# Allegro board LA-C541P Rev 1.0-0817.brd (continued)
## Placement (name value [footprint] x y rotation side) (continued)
CC192  1U_0402_6.3V6K  [C_0402]  197.4 74.87 90 bottom
CC193  1U_0402_6.3V6K  [C_0402]  191.85 70.69 0 bottom
CC194  1U_0402_6.3V6K  [C_0402]  191.85 69.8 0 bottom
CC195  1U_0402_6.3V6K  [C_0402]  218.14 72.2 90 top
CC196  10U_0603_6.3V6M  [C_0603]  217.32 64.98 315 top
CC197  10U_0603_6.3V6M  [C_0603]  218.21 65.87 315 top
CC198  10U_0603_6.3V6M  [C_0603]  219.1 66.76 315 top
CC199  10U_0603_6.3V6M  [C_0603]  219.99 67.65 315 top
CC200  10U_0603_6.3V6M  [C_0603]  220.88 68.54 315 top
CC201  10U_0603_6.3V6M  [C_0603]  217.4 65.03 315 bottom
CC202  10U_0603_6.3V6M  [C_0603]  218.29 65.92 315 bottom
CC203  1U_0402_6.3V6K  [C_0402]  213.19 62.94 90 top
CC204  1U_0402_6.3V6K  [C_0402]  214.08 62.94 90 top
CC205  1U_0402_6.3V6K  [C_0402]  214.97 62.94 90 top
CC208  22U_0603_6.3V6M  [C_0603]  219.18 66.81 315 bottom
CC209  1U_0402_6.3V6K  [C_0402]  166.22 25.72 90 bottom
CC210  1U_0402_6.3V6K  [C_0402]  165.21 25.72 90 bottom
CC211  22U_0603_6.3V6M  [C_0603]  220.07 67.7 315 bottom
CC212  22U_0603_6.3V6M  [C_0603]  217.72 68.23 45 bottom
CC213  22U_0603_6.3V6M  [C_0603]  220.96 68.59 315 bottom
CC269  0.1U_0402_25V6  [C_0402]  156.87 14.04 90 top
CC272  22U_0603_6.3V6M  [C_0603]  195.5 73.74 180 bottom
CC273  220P_0402_25V8J  [C_0402]  201.02 103.54 270 top
CD2  1U_0402_6.3V6K  [C_0402]  136.44 82.3 270 top
CD3  1U_0402_6.3V6K  [C_0402]  136.44 83.16 90 top
CD4  1U_0402_6.3V6K  [C_0402]  136.44 76.97 270 top
CD5  1U_0402_6.3V6K  [C_0402]  136.63 62.43 90 top
CD6  1U_0402_6.3V6K  [C_0402]  136.55 44.74 270 top
CD7  10U_0603_6.3V6M  [C_0603]  136.25 86.41 270 top
CD8  10U_0603_6.3V6M  [C_0603]  136.25 87.37 90 top
CD9  10U_0603_6.3V6M  [C_0603]  136.12 67.43 90 top
CD10  10U_0603_6.3V6M  [C_0603]  136.11 52.41 270 top
CD11  10U_0603_6.3V6M  [C_0603]  136.36 45.68 90 top
CD12  10U_0603_6.3V6M  [C_0603]  136.36 22.37 270 top
CD13  10U_0603_6.3V6M  [C_0603]  140.19 44.66 270 top
CD14  330U_D2_2V_Y  [C_D2]  142.01 21.4 90 top
CD15  10U_0603_6.3V6M  [C_0603]  136.63 32.34 270 top
CD16  0.1U_0402_10V6K  [C_0402]  103.99 40.08 90 top
CD17  1U_0402_6.3V6K  [C_0402]  104.5 76.54 270 top
CD18  10U_0603_6.3V6M  [C_0603]  138.66 33.48 90 top
CD19  1U_0402_6.3V6K  [C_0402]  105.57 75.01 0 top
CD20  1U_0402_6.3V6K  [C_0402]  137.52 33.47 90 top
CD21  0.1U_0402_10V6K  [C_0402]  136.44 79.61 90 top
CD22  2.2U_0402_6.3V6M  [C_0402]  136.44 78.74 270 top
CD23  1U_0402_6.3V6K  [C_0402]  136.5 39.47 270 top
CD24  1U_0402_6.3V6K  [C_0402]  136.76 24.07 90 top
CD25  330U_D2_2V_Y  [C_D2]  98.59 5.93 180 top
CD26  2.2U_0402_6.3V6M  [C_0402]  123.17 88.97 90 top
CD27  10U_0603_6.3V6M  [C_0603]  138.92 24.09 90 top
CD28  10U_0603_6.3V6M  [C_0603]  138.92 39.45 270 top
CD29  0.1U_0402_10V6K  [C_0402]  122.28 88.97 90 top
CD30  1U_0402_6.3V6K  [C_0402]  132.38 89.16 90 top
CD31  10U_0603_6.3V6M  [C_0603]  140.19 39.45 270 top
CD32  10U_0603_6.3V6M  [C_0603]  137.65 39.45 270 top
CD33  1U_0402_6.3V6K  [C_0402]  97.41 76.31 270 top
CD34  10U_0603_6.3V6M  [C_0603]  137.9 32.34 270 top
CD35  1U_0402_6.3V6K  [C_0402]  98.4 76.3 270 top
CD36  1U_0402_6.3V6K  [C_0402]  131.25 89.17 90 top
CD37  10U_0603_6.3V6M  [C_0603]  123.72 89.05 90 bottom
CD38  10U_0603_6.3V6M  [C_0603]  122.45 89.05 90 bottom
CD39  10U_0603_6.3V6M  [C_0603]  106.6 71.9 180 top
CD40  1U_0402_6.3V6K  [C_0402]  106.61 61.62 180 top
CD41  1U_0402_6.3V6K  [C_0402]  106.4 51.25 90 top
CD42  1U_0402_6.3V6K  [C_0402]  107.29 45.69 270 top
CD43  330U_D2_2V_Y  [C_D2]  151.38 51.3 0 top
CD44  2.2U_0402_6.3V6M  [C_0402]  120.71 7.13 180 top
CD45  10U_0603_6.3V6M  [C_0603]  103.99 45.8 90 top
CD46  10U_0603_6.3V6M  [C_0603]  103.99 43.14 90 top
CD47  0.1U_0402_10V6K  [C_0402]  120.71 6.24 180 top
CD48  1U_0402_6.3V6K  [C_0402]  105.57 74.12 0 top
CD49  10U_0603_6.3V6M  [C_0603]  107.1 60.47 180 top
CD50  10U_0603_6.3V6M  [C_0603]  107.1 37.99 180 top
CD51  1U_0402_6.3V6K  [C_0402]  96.37 76.3 270 top
CD52  10U_0603_6.3V6M  [C_0603]  107.36 49.55 180 top
CD53  1U_0402_6.3V6K  [C_0402]  95.36 76.3 270 top
CD54  1U_0402_6.3V6K  [C_0402]  105.71 77.36 0 top
CD55  10U_0603_6.3V6M  [C_0603]  94.21 76.41 270 top
CD56  10U_0603_6.3V6M  [C_0603]  92.82 76.41 270 top
CD57  10U_0603_6.3V6M  [C_0603]  105.2 43.14 90 top
CD58  1U_0402_6.3V6K  [C_0402]  106.61 65.55 180 top
CD59  1U_0402_6.3V6K  [C_0402]  106.28 43 90 top
CD60  1U_0402_6.3V6K  [C_0402]  106.28 46.55 90 top
CD61  330U_D2_2V_Y  [C_D2]  102.88 5.93 0 top
CD62  2.2U_0402_6.3V6M  [C_0402]  107.92 88.92 0 bottom
CD63  10U_0603_6.3V6M  [C_0603]  106.6 66.7 180 top
CD64  10U_0603_6.3V6M  [C_0603]  105.2 45.8 90 top
CD65  0.1U_0402_10V6K  [C_0402]  108.75 89.8 90 bottom
CD66  1U_0402_6.3V6K  [C_0402]  100.89 77.49 180 top
CD67  10U_0603_6.3V6M  [C_0603]  107.23 30.75 180 top
CD68  10U_0603_6.3V6M  [C_0603]  104.25 51.26 90 top
CD69  1U_0402_6.3V6K  [C_0402]  110.59 88.92 180 bottom
CD70  10U_0603_6.3V6M  [C_0603]  106.6 69.62 180 top
CD71  1U_0402_6.3V6K  [C_0402]  112.06 88.91 90 bottom
CD72  1U_0402_6.3V6K  [C_0402]  101.96 76.54 270 top
CD73  10U_0603_6.3V6M  [C_0603]  111.15 90 180 bottom
CD74  10U_0603_6.3V6M  [C_0603]  111.14 91.21 180 bottom
CD75  2.2U_0402_6.3V6M  [C_0402]  137.01 58.87 90 top
CD76  0.1U_0402_10V6K  [C_0402]  139.68 58.87 90 top
CD77  2.2U_0402_6.3V6M  [C_0402]  141.46 58.87 90 top
CD78  0.1U_0402_10V6K  [C_0402]  140.57 58.87 90 top
CD79  2.2U_0402_6.3V6M  [C_0402]  107.37 56.79 180 top
CD80  0.1U_0402_10V6K  [C_0402]  107.29 57.86 90 top
CD81  2.2U_0402_6.3V6M  [C_0402]  105.26 57.86 90 top
CD82  0.1U_0402_10V6K  [C_0402]  106.28 57.86 90 top
CD89  10U_0603_6.3V6M  [C_0603]  137.65 22.44 270 top
CD90  10U_0603_6.3V6M  [C_0603]  137.39 52.41 270 top
CD91  10U_0603_6.3V6M  [C_0603]  138.66 63.84 270 top
CD92  0.1U_0402_10V6K  [C_0402]  107.2 40.93 180 top
CD93  1U_0402_6.3V6K  [C_0402]  136.04 33.35 90 top
CD94  1U_0402_6.3V6K  [C_0402]  138.03 44.8 270 top
CD95  1U_0402_6.3V6K  [C_0402]  137.19 53.36 0 top
CD96  1U_0402_6.3V6K  [C_0402]  139.04 44.8 270 top
CD97  1U_0402_6.3V6K  [C_0402]  137.27 67.63 90 top
CD98  10U_0603_6.3V6M  [C_0603]  103.23 76.54 270 top
CD99  10U_0603_6.3V6M  [C_0603]  140.19 45.93 90 top
CD100  1U_0402_6.3V6K  [C_0402]  137.77 24.07 90 top
CD101  1U_0402_6.3V6K  [C_0402]  139.04 45.79 90 top
CD102  1U_0402_6.3V6K  [C_0402]  137.52 65.88 270 top
CD103  1U_0402_6.3V6K  [C_0402]  136.63 65.88 270 top
CD104  1U_0402_6.3V6K  [C_0402]  138.03 45.79 90 top
CD105  10U_0603_6.3V6M  [C_0603]  129.96 89.17 90 top
CD106  10U_0603_6.3V6M  [C_0603]  107.23 29.48 180 top
CD107  10U_0603_6.3V6M  [C_0603]  106.66 23.64 180 top
CD108  1U_0402_6.3V6K  [C_0402]  107.29 43 90 top
CD109  1U_0402_6.3V6K  [C_0402]  106.99 28.34 180 top
CD110  1U_0402_6.3V6K  [C_0402]  106.67 22.5 180 top
CD111  1U_0402_6.3V6K  [C_0402]  107.42 51.25 90 top
CD112  1U_0402_6.3V6K  [C_0402]  107.12 36.85 180 top
CD113  10U_0603_6.3V6M  [C_0603]  105.71 76.09 0 top
CD114  10U_0603_6.3V6M  [C_0603]  107.1 63.65 180 top
CD115  10U_0603_6.3V6M  [C_0603]  106.9 25.82 180 top
CD116  1U_0402_6.3V6K  [C_0402]  106.28 45.69 270 top
CD117  1U_0402_6.3V6K  [C_0402]  105.39 51.25 90 top
CD118  1U_0402_6.3V6K  [C_0402]  106.23 70.76 180 top
CD119  1U_0402_6.3V6K  [C_0402]  106.61 62.5 180 top
CD120  1U_0402_6.3V6K  [C_0402]  106.98 26.9 180 top
CD121  10U_0603_6.3V6M  [C_0603]  100.69 76.54 270 top
CD122  0.1U_0402_10V6K  [C_0402]  107.29 39.97 270 top
CD123  0.1U_0402_10V6K  [C_0402]  107.24 41.93 180 top
CD124  0.1U_0402_10V6K  [C_0402]  104.96 41.93 180 top
CD127  0.022U_0402_16V7K  [C_0402]  138.79 56.23 270 top
CD128  0.1U_0402_10V6K  [C_0402]  138.79 58.87 90 top
CD129  0.1U_0402_10V6K  [C_0402]  137.52 62.43 90 top
CD136  0.022U_0402_16V7K  [C_0402]  136.55 6.17 90 top
CD137  0.1U_0402_10V6K  [C_0402]  134.77 7.08 270 top
CD138  0.1U_0402_10V6K  [C_0402]  133.88 7.08 270 top
CD139  0.1U_0402_10V6K  [C_0402]  130.33 7.08 270 top
CD140  0.1U_0402_10V6K  [C_0402]  132.99 7.08 270 top
CD142  0.1U_0402_10V6K  [C_0402]  107.29 46.55 90 top
CD143  0.1U_0402_10V6K  [C_0402]  107.37 55.9 180 top
CD144  0.1U_0402_25V6  [C_0402]  48.04 13.23 180 top
CE1  27P_0402_50V8J  [C_0402]  173.79 118.89 180 bottom
CE6  4.7U_0805_25V6-K  [C_0805]  206.35 144.63 270 bottom
CE8  4.7P_0402_50V8C  [C_0402]  179.79 148.43 270 top
CE9  4.7P_0402_50V8C  [C_0402]  178.52 148.43 270 top
CH4  12P_0402_50V8J  [C_0402]  134.9 134.69 90 top
CH5  15P_0402_50V8J  [C_0402]  134.9 133.82 270 top
CH10  0.1U_0402_25V6  [C_0402]  145.35 123.72 90 top
CH13  15P_0402_50V8J  [C_0402]  138.98 99.58 270 top
CH14  15P_0402_50V8J  [C_0402]  138.96 100.42 90 top
CH17  0.1U_0402_25V6  [C_0402]  191.24 106.19 180 top
CH29  22U_0805_6.3VAM  [C_0805]  133.98 97.19 90 top
CH31  1U_0402_6.3VAK  [C_0402]  128.28 112.62 180 bottom
CH32  1U_0402_6.3VAK  [C_0402]  137.06 96.87 90 top
CH33  1U_0402_6.3VAK  [C_0402]  144.56 127.34 0 top
CH34  1U_0402_6.3VAK  [C_0402]  123.66 108.22 0 bottom
CH35  1U_0402_6.3VAK  [C_0402]  139.5 127.27 180 bottom
CH36  1U_0402_6.3VAK  [C_0402]  133.47 113.56 90 bottom
CH37  1U_0402_6.3VAK  [C_0402]  126.29 127.35 0 bottom
CH38  1U_0402_6.3VAK  [C_0402]  138.95 126.34 180 bottom
CH40  1U_0402_6.3VAK  [C_0402]  134.61 129.56 180 bottom
CH41  1U_0402_6.3VAK  [C_0402]  133.39 132.43 180 bottom
CH42  12P_0402_50V8J  [C_0402]  131.3 133.93 90 bottom
CH44  22U_0805_6.3VAM  [C_0805]  137.08 117.08 270 bottom
CH45  22U_0805_6.3VAM  [C_0805]  137.41 118.25 90 bottom
CH46  22U_0805_6.3VAM  [C_0805]  135.72 97.19 90 top
CH47  22U_0603_6.3V6M  [C_0603]  124.88 103.65 0 bottom
CH49  12P_0402_50V8J  [C_0402]  132.19 133.93 90 bottom
CH50  12P_0402_50V8J  [C_0402]  129.14 133.93 90 bottom
CH51  12P_0402_50V8J  [C_0402]  130.03 133.93 90 bottom
CH62  0.1U_0402_25V6  [C_0402]  114.31 118.02 180 bottom
CH63  0.1U_0402_25V6  [C_0402]  112.41 123.86 180 bottom
CH64  0.1U_0402_25V6  [C_0402]  112.68 114.19 0 bottom
CH65  0.1U_0402_25V6  [C_0402]  144.56 128.23 0 top
CH66  0.1U_0402_25V6  [C_0402]  133.16 119.11 270 bottom
CH67  0.1U_0402_25V6  [C_0402]  126.29 128.24 0 bottom
CH68  0.1U_0402_25V6  [C_0402]  121.83 122.37 0 bottom
CH266  0.01U_0402_16V7K  [C_0402]  132.27 126.39 90 bottom
CH267  1U_0402_6.3VAK  [C_0402]  109.97 100.99 180 top
CH268  22P_0402_50V8J  [C_0402]  143.06 124.86 180 bottom
CH269  0.1U_0402_25V6  [C_0402]  136.17 128.1 0 bottom
CMOS1  SHORT PADS~D  [SHORTPADS]  134.6 128.42 0 bottom
CN63  0.22U_0402_10V6K  [C_0402]  27.74 33.85 270 top
CN64  0.22U_0402_10V6K  [C_0402]  27.92 24.35 90 top
CN65  0.22U_0402_10V6K  [C_0402]  38.2 33.79 270 top
CN66  0.22U_0402_10V6K  [C_0402]  39.5 24.12 90 top
CN67  0.1U_0402_10V6K  [C_0402]  23.3 27.5 270 top
CN69  0.22U_0402_10V6K  [C_0402]  25.71 33.85 270 top
CN70  0.22U_0402_10V6K  [C_0402]  28.63 33.85 270 top
CN71  0.01U_0402_16V7K  [C_0402]  40.01 32.89 90 top
CN72  0.22U_0402_10V6K  [C_0402]  27.03 24.35 90 top
CN73  0.1U_0402_10V6K  [C_0402]  34.17 25.83 180 top
CN74  0.22U_0402_10V6K  [C_0402]  36.41 33.76 270 top
CN75  0.01U_0402_16V7K  [C_0402]  29.82 33.19 0 top
CN76  0.22U_0402_10V6K  [C_0402]  26.6 33.85 270 top
CN79  0.22U_0402_10V6K  [C_0402]  39.09 33.79 270 top
CN80  0.22U_0402_10V6K  [C_0402]  37.3 33.76 270 top
CN81  0.22U_0402_10V6K  [C_0402]  38.61 24.12 90 top
CN83  0.22U_0402_10V6K  [C_0402]  14.95 9.11 270 top
CN85  0.22U_0402_10V6K  [C_0402]  14.06 9.11 270 top
CN87  0.22U_0402_10V6K  [C_0402]  12.09 8.99 270 top
CN88  0.22U_0402_10V6K  [C_0402]  11.2 8.99 270 top
CN91  0.22U_0402_10V6K  [C_0402]  8.09 7.46 270 top
CN92  0.22U_0402_10V6K  [C_0402]  8.98 7.46 270 top
CN95  0.22U_0402_10V6K  [C_0402]  5.02 7.75 270 top
CN97  0.22U_0402_10V6K  [C_0402]  5.91 7.75 270 top
CPU1  SKL-H_BGA1440  [SKL-H_BGA_1440P-T]  171.69 64.71 180 top
CV27  0.01U_0402_16V7K  [C_0402]  153.19 117.3 0 top
CV28  0.1U_0402_25V6  [C_0402]  162.54 114.92 180 top
CV29  0.1U_0402_25V6  [C_0402]  162.54 117.46 180 top
CV30  0.01U_0402_16V7K  [C_0402]  164.24 115.08 0 bottom
CV31  0.1U_0402_25V6  [C_0402]  156.52 113.3 90 top
CV42  2.2U_0402_6.3V6M  [C_0402]  155.37 113.3 90 top
CZ1  0.22U_0402_10V6K  [C_0402]  331.64 42.56 270 bottom
CZ2  0.22U_0402_10V6K  [C_0402]  330.75 42.56 270 bottom
CZ3  0.1U_0402_10V7K  [C_0402]  212.23 120.29 0 top
CZ4  0.1U_0402_25V6  [C_0402]  195.75 126.37 90 bottom
CZ5  0.1U_0402_25V6  [C_0402]  189.46 126.59 90 top
CZ6  0.1U_0402_25V6  [C_0402]  191.37 133.83 270 top
CZ7  0.1U_0402_25V6  [C_0402]  192.38 133.83 270 top
CZ8  10U_0603_25V6M  [C_0603]  189.46 124.54 270 bottom
CZ9  0.1U_0402_25V6  [C_0402]  190.07 134.79 90 bottom
CZ10  0.1U_0402_25V6  [C_0402]  64.73 42.17 90 top
CZ11  0.1U_0402_25V6  [C_0402]  74.57 41.66 90 top
CZ12  0.1U_0402_25V6  [C_0402]  74.63 39.19 0 top
CZ15  10U_0603_25V6M  [C_0603]  196.89 126.64 90 bottom
CZ25  0.1U_0402_10V7K  [C_0402]  327.74 45.49 270 top
CZ26  0.1U_0402_10V7K  [C_0402]  326.85 45.49 270 top
CZ30  100P_0402_50V8J  [C_0402]  289.14 33.37 270 top
CZ31  100P_0402_50V8J  [C_0402]  289.14 34.23 90 top
CZ57  0.047U_0402_16V4Z  [C_0402]  74.57 43.44 90 top
CZ58  0.1U_0402_10V7K  [C_0402]  212.23 119.34 0 top
CZ63  0.1U_0402_10V7K  [C_0402]  191.7 101.37 180 top
CZ65  33P_0402_50V8J  [C_0402]  335.88 24.09 90 bottom
CZ66  33P_0402_50V8J  [C_0402]  335.88 23.07 270 bottom
CZ67  33P_0402_50V8J  [C_0402]  335.88 21.17 270 bottom
CZ82  0.1U_0402_10V7K  [C_0402]  199.2 97.89 0 top
CZ86  0.1U_0402_10V7K  [C_0402]  203.31 100.78 90 top
CZ88  1U_0402_6.3V6K  [C_0402]  203.32 99.49 270 top
CZ89  0.1U_0402_10V7K  [C_0402]  187.3 98.27 270 top
CZ90  1U_0402_6.3V6K  [C_0402]  187.3 99.64 90 top
CZ91  0.22U_0402_10V6K  [C_0402]  331.83 44.62 270 top
CZ92  0.22U_0402_10V6K  [C_0402]  332.72 44.62 270 top
CZ93  .1U_0402_16V7K  [C_0402]  325.78 41.35 90 top
CZ94  .1U_0402_16V7K  [C_0402]  334.34 40.18 90 top
CZ95  0.1U_0402_10V7K  [C_0402]  90.48 18.56 180 top
CZ96  0.1U_0402_10V7K  [C_0402]  90.28 23.69 90 top
CZ97  1U_0402_6.3V6K  [C_0402]  91.29 23.69 90 top
D7  -  [RB751VM-40TE-17_SOD323-2]  158.35 74.47 90 top
D8  -  [RB751VM-40TE-17_SOD323-2]  146.32 74.28 90 top
D18  -  [RB751VM-40TE-17_SOD323-2]  151.47 74.28 90 top
D20  -  [L30ESDL5V0C3-2_SOT23-3]  116.16 136.16 90 bottom
D21  -  [PESD5V0U2BT_SOT23-3]  103.55 138.09 0 bottom
D22  -  [PESD5V0U2BT_SOT23-3]  115.66 145.5 0 bottom
D31  -  [RB751S40T1G_SOD523-2]  219.39 112.86 0 top
D32  -  [RB751S40T1G_SOD523-2]  194.16 143.91 180 bottom
D33  -  [L30ESD24VC3-2_SOT23-3]  211.33 144.42 270 bottom
D36  -  [RB751S40T1G_SOD523-2]  219.39 114.01 0 top
D59  -  [RB751S40T1G_SOD523-2]  302.79 6.88 90 top
D62  -  [RB751S40T1G_SOD523-2]  301.4 6.88 90 top
D64  -  [RB751VM-40TE-17_SOD323-2]  110.93 144.33 0 bottom
D65  -  [RB751VM-40TE-17_SOD323-2]  110.93 145.92 0 bottom
D66  -  [RB751VM-40TE-17_SOD323-2]  109.08 150.47 180 bottom
D68  -  [RB751VM-40TE-17_SOD323-2]  109.08 153.77 180 bottom
D69  -  [RB751VM-40TE-17_SOD323-2]  110.93 147.51 0 bottom
D71  -  [RB751VM-40TE-17_SOD323-2]  109.08 152.12 180 bottom
D90  -  [RB751S40T1G_SOD523-2]  269.47 43.57 315 top
D92  -  [RB751VM-40TE-17_SOD323-2]  116.67 148.41 180 bottom
D93  -  [BAT54CW_SOT323-3]  123.11 146.52 0 bottom
D94  -  [RB751VM-40TE-17_SOD323-2]  209.02 68.95 90 top
D95  -  [RB751VM-40TE-17_SOD323-2]  165.59 63.55 90 bottom
D97  -  [RB751S40T1G_SOD523-2]  301.48 5.39 0 top
D98  -  [RB751S40T1G_SOD523-2]  301.49 4.21 0 top
D99  -  [RB751S40T1G_SOD523-2]  304.88 5.46 0 top
D100  -  [RB751S40T1G_SOD523-2]  297.86 5.56 270 top
DZ1  -  [RB751S40T1G_SOD523-2]  320.06 26.82 0 top
DZ2  -  [RB751S40T1G_SOD523-2]  320.06 29.48 0 top
DZ3  -  [RB751S40T1G_SOD523-2]  64.57 46.78 90 top
FD1  FIDUCIAL MARK~D  [FIDUCIAL_C40M80]  249.91 148.23 0 top
FD2  FIDUCIAL MARK~D  [FIDUCIAL_C40M80]  256.25 126.39 180 bottom
FD3  FIDUCIAL MARK~D  [FIDUCIAL_C40M80]  3.52 16.47 0 top
FD4  FIDUCIAL MARK~D  [FIDUCIAL_C40M80]  27.25 8.07 180 bottom
H1  -  [H_3P8]  168.9 15.5 0 top
H2  -  [H_3P8]  204 17.3 0 top
H3  -  [H_3P8]  204 71.7 0 top
H4  -  [H_3P8]  168.9 72.6 0 top
H5  -  [H_2P8]  190 13.7 0 top
H6  -  [H_2P8]  119.4 154.1 0 top
H7  -  [H_2P8]  93.3 111.6 0 top
H9  -  [H_2P8]  27.9 49.6 0 top
H10  -  [H_2P8]  233 141.6 0 top
H12  -  [H_3P3]  145.99 148.75 0 top
H13  -  [H_2P8]  235.8 98.6 0 top
H14  -  [H_3P8]  44.5 23.6 0 top
H15  -  [H_2P1]  41 5.1 0 top
H17  -  [H_2P8]  255.5 144.7 0 top
H18  -  [H_2P8]  45.5 5.1 0 top
H19  -  [H_2P8]  272.9 7.5 0 top
H20  -  [H_2P8]  331.5 6.8 0 top
H22  -  [H_2P8]  253.5 63.6 0 top
H23  -  [H_3P8]  305.5 20 0 top
H27  -  [H_3P3]  138.31 138.86 0 top
H29  -  [H_2P6X2P1]  255.5 149.2 90 top
H30  -  [H_2P8]  347 62.1 0 top
H31  -  [H_2P6X2P1N]  353 13.6 0 top
JAPS1  ACES_50506-01841-P01  [ACES_50506-01841-P01_18P]  226.48 96.37 180 bottom
JDEG2  ACES_50506-01041-P01  [ACES_50506-01041-P01_10P]  184.66 101.68 180 bottom
JDEG3  ACES_50228-0067N-001  [ACES_50228-0067N-001_6P]  264.25 59.34 315 top
JDIMM1  BELLW_80888-6021  [BELLW_80888-6021_260P-T]  132.8 15.17 90 top
JDIMM2  LOTES_ADDR0106-P005A  [LOTES_ADDR0106-P005A_260P-T]  124.6 15.17 90 bottom
JDIMM3  BELLW_80888-2021  [BELLW_80888-2021_260P-T]  118.8 15.17 90 top
JDIMM4  LOTES_ADDR0107-P005A  [LOTES_ADDR0107-P005A_260P-T]  110.6 15.17 270 bottom
JDOCK1  FOX_QL01723-D265G1-8H  [FOX_QL01723-D265G1-8H_144P]  157.75 148 0 bottom
JEDP1  ACES_50398-04041-001  [ACES_50398-04041-001_40P]  127.39 141.62 170 top
JFAN1  ACES_50273-0040N-001  [ACES_50273-0040N-001_4P]  91.5 94.35 90 top
JFAN2  ACES_50273-0040N-001  [ACES_50273-0040N-001_4P]  273.18 49.56 330 top
JIO1  FOX_QT50A01-29100-9H  [FOX_QT50A01-29100-9H_100P-T-S]  315.24 48.3 270 top
JIO2  FOX_QT50A61-29100-9H  [FOX_QT50A61-29100-9H_160P-T-S]  55.91 22.35 90 top
JKBTP1  ACES_50559-02001-001  [ACES_50559-02001-001_20P]  291.87 35.35 270 top
JLED1  ACES_50554-00641-001  [ACES_50554-00641-001_6P-T]  291.05 4.93 0 top
JLOM1  SINGA_2RJ1672-000111F  [SINGA_2RJ1672-000111F_13P]  235.13 147.47 180 top
JLPDE1  ACES_50506-01041-P01  [ACES_50506-01041-P01_10P]  204.64 127.18 90 bottom
JMXM1  JAE_MM70-314-310B1-1-R300  [JAE_MM70-314-310B1-1-_310P-S]  223.5 87.95 180 top
JNGFF1  BELLW_80148-4221  [BELLW_80148-4221_67P]  212.72 128.7 270 bottom
JNGFF2  BELLW_80149-3221  [BELLW_80149-3221_67P]  328.47 23.43 90 bottom
JNGFF3  BELLW_80159-3221  [BELLW_80159-3221_67P]  2.75 4.07 0 bottom
JPB1  ACES_50228-0067N-001  [ACES_50228-0067N-001_6P]  290 44.4 0 top
JRTC1  ACES_50271-0020N-001  [ACES_50271-0020N-001_2P]  50.9 27.85 270 bottom
JSATA2  STARC_7300L30-100000-G4  [STARC_7300L30-100000-G4_30P-T]  44.05 18.93 0 bottom
JSIM1  T-SOL_159-1000302602  [T-SOL_159-1000302602_10P]  339.78 26.14 270 bottom
JSPI1  E-T_6712K-Y20N-07L  [E-T_6712K-Y20N-07L_20P]  157.12 124.57 0 bottom
JTAG1  @SHORT PADS~D  [SHORTPADS]  192.27 122.01 0 bottom
JTS1  ACES_50228-0067N-001  [ACES_50228-0067N-001_6P]  134.3 130.72 180 top
JUART1  ACES_50207-00471-P01  [ACES_50207-00471-P01_4P-T]  109.83 118.1 270 bottom
JUSH1  ACES_50559-02601-001  [ACES_50559-02601-001_26P-T]  68.05 45.8 270 top
JXDP1  SAMTE_BSH-030-01-L-D-A  [SAMTE_BSH-030-01-L-D-A_60P]  144.36 4.59 0 top
L10  MCM1012B900F06BP_4P  [INPAQ_MCM1012B900F06BP_4P]  103.8 132.81 90 bottom
L11  MCM1012B900F06BP_4P  [INPAQ_MCM1012B900F06BP_4P]  116.25 140.47 270 bottom
L29  4.7UH_BRC2012T4R7MD_20%  [TAIYO_BRC2012T4R7MD_2P]  242.42 112.14 270 top
LED5  LTW-270US5_WHITE  [LED_LTW-270US5_2P]  254.06 81.87 0 top
NOREF  -  []  27.9 49.6 0 top
NOREF#2  -  []  41 5.1 0 top
NOREF#3  -  []  41 5.1 0 top
NOREF#4  -  []  347 62.1 0 top
NOREF#5  -  []  97.95 71.6 270 top
NOREF#6  -  []  204.24 -10.47 0 top
NOREF#7  -  []  138.31 138.86 0 top
NOREF#8  -  []  331.5 6.8 0 top
NOREF#9  -  []  190 13.7 0 top
NOREF#10  -  []  41 5.1 0 top
NOREF#11  -  []  233 141.6 180 top
NOREF#12  -  []  159.41 -37.84 0 top
NOREF#13  -  []  253.5 63.6 0 top
NOREF#14  -  []  41 5.1 0 top
NOREF#15  -  []  168.9 15.5 0 top
NOREF#16  -  []  204 71.7 0 top
NOREF#17  -  []  93.3 111.6 0 top
NOREF#18  -  []  41 5.1 0 top
NOREF#19  -  []  235.8 98.6 0 top
NOREF#20  -  []  75.54 31.01 0 top
NOREF#21  -  []  44.5 23.6 0 top
NOREF#22  -  []  168.9 72.6 0 top
NOREF#23  -  []  45.5 5.1 0 top
NOREF#24  -  []  255.5 144.7 0 top
NOREF#25  -  []  270.49 13.42 0 top
NOREF#26  -  []  145.99 148.75 0 top
NOREF#27  -  []  41 5.1 0 top
NOREF#28  -  []  305.5 20 0 top
NOREF#29  -  []  41 5.1 0 top
NOREF#30  -  []  119.4 154.1 0 top
NOREF#31  -  []  272.9 7.5 0 top
NOREF#32  -  []  75.4 70.84 0 top
NOREF#33  -  []  41 5.1 0 top
NOREF#34  -  []  41 5.1 0 top
NOREF#35  -  []  204 17.3 0 top
NOREF#36  -  []  150.74 229.71 0 top
NOREF#37  -  []  151.7 41.45 180 bottom
NOREF#38  -  []  6.71 26.02 180 bottom
NOREF#39  -  []  10.46 64.54 270 bottom
NOREF#40  -  []  6.71 35.16 180 bottom
NOREF#41  -  []  98.96 87.6 90 bottom
NOREF#42  -  []  76.99 63.65 90 bottom
PBATT1  SUYIN_200045GR009M28QZR  [SUYIN_200045GR009M28QZR_9P]  248.45 2.3 0 top
PC1  100U_25V_M  [C_EEEFK1E101YP]  233.02 83.88 90 top
PC2  1U_0603_10V4Z  [C_0603]  48.29 28.91 90 bottom
PC4  2200P_0402_50V7K  [C_0402]  263.61 6.32 180 top
PC5  1500P_0402_50V7K  [C_0402]  247.43 13.29 180 top
PC9  0.022U_0603_50V7K  [C_0603]  44.78 42.84 90 bottom
PC11  1000P_0402_50V7K  [C_0402]  49.25 48.9 90 bottom
PC14  10U_0805_25V6K  [C_0805]  32.25 45.64 270 bottom
PC15  0.1U_0603_25V7K  [C_0603]  49.05 44.34 270 bottom
PC30  10U_0805_25V6K  [C_0805]  236.17 81.44 0 top
PC31  0.1U_0603_25V7K  [C_0603]  236.5 82.95 0 top
PC100  4.7U_0603_10V6K  [C_0603]  346.04 32.79 270 top
PC101  10U_0805_25V6K  [C_0805]  345.15 35.61 270 top
PC102  10U_0805_25V6K  [C_0805]  339.22 26.5 0 top
PC103  0.1U_0402_25V6  [C_0402]  347.5 35.45 0 top
PC105  2200P_0402_50V7K  [C_0402]  346.54 35.47 270 top
PC109  0.1U_0603_25V7K  [C_0603]  349.66 26.63 0 top
PC110  0.1U_0603_25V7K  [C_0603]  350.25 35.55 270 top
PC111  680P_0603_50V7K  [C_0603]  345.47 26.63 180 top
PC114  680P_0603_50V7K  [C_0603]  353.91 37.23 270 top
PC117  0.1U_0603_25V7K  [C_0603]  352.23 30.73 90 bottom
PC118  4.7U_0603_10V6K  [C_0603]  354.1 31.14 90 top
PC119  1U_0603_10V6K  [C_0603]  347.37 28.51 180 top
PC120  330U_D2E_6.3VM_R25M  [C_D2E]  342.48 9.35 0 top
PC121  330U_D2E_6.3VM_R25M  [C_D2E]  351.62 45.62 270 bottom
PC151  0.1U_0402_10V7K  [C_0402]  335.88 41.4 90 top
PC201  220U_D2_2VY_R17M  [C_D2]  62.38 30.83 270 top
PC202  10U_0805_25V6K  [C_0805]  73.22 17.17 0 bottom
PC203  10U_0805_25V6K  [C_0805]  73.22 18.94 0 bottom
PC204  0.1U_0402_25V6  [C_0402]  74.05 20.28 0 bottom
PC205  2200P_0402_50V7K  [C_0402]  74.05 21.17 0 bottom
PC206  0.22U_0603_10V7K  [C_0603]  62.76 19.2 0 bottom
PC207  22U_0805_6.3VAM  [C_0805]  61.66 13.48 180 bottom
PC209  0.033U_0402_16V7K  [C_0402]  58.78 14.33 270 bottom
PC210  1U_0603_10V6K  [C_0603]  56.6 20.21 90 bottom
PC211  220P_0402_50V8J  [C_0402]  57.05 16.1 270 top
PC212  680P_0603_50V7K  [C_0603]  63.84 17.23 0 top
PC213  1U_0603_10V6K  [C_0603]  59.21 20.91 180 bottom
PC214  .1U_0402_16V7K  [C_0402]  57.89 14.33 270 bottom
PC215  1U_0402_6.3VX5R  [C_0402]  57.67 17.86 0 top
PC300  2200P_0402_50V7K  [C_0402]  333.09 13.29 0 top
PC301  680P_0603_50V7K  [C_0603]  328 13.04 90 top
PC302  0.1U_0603_25V7K  [C_0603]  326.35 21.1 90 top
PC303  10U_0805_25V6K  [C_0805]  332.6 14.69 180 top
PC304  330P_0402_50V7K  [C_0402]  333.84 23.59 270 top
PC305  47U_0805_6.3V6M  [C_0805]  321.72 14.02 270 top
PC306  47U_0805_6.3V6M  [C_0805]  316.38 14.02 270 top
PC307  22U_0805_6.3VAM  [C_0805]  319.94 14.02 270 top
PC308  22U_0805_6.3VAM  [C_0805]  318.16 14.02 270 top
PC309  4.7U_0603_6.3V6K  [C_0603]  331.11 20.53 0 top
PC310  4.7U_0603_6.3V6K  [C_0603]  333.65 19.9 90 top
PC311  0.1U_0402_25V6  [C_0402]  332.19 13.29 180 top
PC312  1000P_0402_50V7K  [C_0402]  328.35 20.72 180 top
PC400  22U_0603_6.3V6M  [C_0603]  12.74 54.06 0 top
PC401  0.1U_0402_16V7K  [C_0402]  18.21 57.69 180 top
PC402  68P_0402_50V8J  [C_0402]  15.96 59.55 180 top
PC403  22U_0603_6.3V6M  [C_0603]  19 60.55 90 top
PC404  22U_0603_6.3V6M  [C_0603]  20.27 60.55 90 top
PC405  680P_0402_50V7K  [C_0402]  15.82 53.36 90 top
PC500  0.1U_0603_25V7K  [C_0603]  75.77 13.44 270 top
PC501  680P_0402_50V7K  [C_0402]  76.99 15.26 0 top
PC502  22U_0603_6.3V6M  [C_0603]  80.14 13.13 90 top
PC503  22U_0603_6.3V6M  [C_0603]  81.4 13.12 90 top
PC504  22U_0603_6.3V6M  [C_0603]  82.66 13.14 90 top
PC505  10U_0603_25V6M  [C_0603]  68.62 9.42 270 top
PC506  1U_0402_6.3V6K  [C_0402]  73.13 12.92 270 top
PC507  0.1U_0402_25V6  [C_0402]  73.4 5.47 270 top
PC508  0.1U_0402_25V6  [C_0402]  71.1 9.18 270 top
PC509  10U_0603_25V6M  [C_0603]  69.96 9.42 270 top
PC510  10U_0603_25V6M  [C_0603]  67.42 9.35 270 top
PC700  0.1U_0603_25V7K  [C_0603]  37.63 34.27 180 bottom
PC702  0.1U_0402_25V6  [C_0402]  277.27 38.17 270 top
PC703  0.1U_0402_25V6  [C_0402]  278.17 37.24 270 top
PC704  0.01U_0402_25V6  [C_0402]  277.28 36.42 270 top
PC705  2200P_0402_50V7K  [C_0402]  290.68 22.66 180 top
PC706  0.1U_0603_25V7K  [C_0603]  290.98 21.58 180 top
PC707  10U_0805_25V6K  [C_0805]  291.13 20.06 180 top
PC708  10U_0805_25V6K  [C_0805]  291.13 18.28 180 top
PC709  1U_0603_25V6K  [C_0603]  280.89 40.25 180 top
PC710  0.1U_0402_25V6  [C_0402]  275.1 26.15 180 top
PC711  0.1U_0402_25V4Z~D  [C_0402]  271.7 37.6 90 top
PC712  0.1U_0402_25V6  [C_0402]  276.08 28.04 270 top
PC713  0.1U_0402_25V6  [C_0402]  273.22 27.12 90 top
PC714  2.2U_0603_10V6K  [C_0603]  277.03 31.45 270 top
PC715  10U_0805_25V5K~D  [C_0805]  270.85 20.12 90 top
PC717  680P_0402_50V7K  [C_0402]  287.81 17.95 90 top
PC718  10U_0805_25V5K~D  [C_0805]  269.07 20.12 90 top
PC719  10U_0805_25V5K~D  [C_0805]  267.58 19.51 180 top
PC720  100P_0402_50V8J  [C_0402]  268.48 36.1 0 top
PC721  100P_0402_50V8J  [C_0402]  270.81 38.39 270 top
PC734  0.047U_0603_50V7  [C_0603]  277.28 33.95 0 top
PC737  100P_0402_50V8J  [C_0402]  268.52 29.87 180 top
PC741  100P_0402_50V8J  [C_0402]  267.6 28.09 0 top
PC800  0.22U_0402_16V7K  [C_0402]  101.31 129.85 90 top
PC801  2200P_0402_50V7K  [C_0402]  99.7 114.17 180 top
PC802  0.1U_0402_25V6  [C_0402]  99.7 115.18 180 top
PC803  10U_0805_25V6K  [C_0805]  99.42 116.61 180 top
PC804  .1U_0603_25V7K  [C_0603]  101.07 123.4 0 top
PC805  1U_0603_10V6K  [C_0603]  99.99 123.4 180 top
PC806  220U_D2_2VY_R17M  [C_D2]  101.02 120.14 90 bottom
PC807  1000P_0402_50V7K  [C_0402]  93.73 117.22 0 top
PC900  1U_0402_6.3V6K  [C_0402]  233.9 90.34 90 bottom
PC901  4.7U_0805_6.3V6K  [C_0805]  231.21 87.9 180 bottom
PC902  .1U_0402_16V7K  [C_0402]  235.87 90.34 90 bottom
PC903  0.01U_0402_25V7K  [C_0402]  234.11 81.02 0 bottom
PC904  22U_0805_6.3V6M  [C_0805]  231.21 85.11 180 bottom
PC1001  0.47U_0805_25V7K~D  [C_0805]  125.3 140.86 90 bottom
PC1002  2200P_0402_50V7K  [C_0402]  285.49 16.66 180 top
PC1003  0.1U_0402_25V6  [C_0402]  286.41 16.66 0 top
PC1004  1U_0603_25V6K  [C_0603]  254.47 13.93 180 top
PC1005  1U_0603_25V6K  [C_0603]  285.71 4.92 180 top
PC1006  0.1U_0603_50V4Z  [C_0603]  330.67 49.04 270 top
PC1007  0.1U_0603_25V7K  [C_0603]  331.88 49.04 270 top
PC1008  0.047U_0603_50V7K  [C_0603]  338.54 51.96 270 top
PC1009  0.1U_0402_25V6  [C_0402]  338.34 52.92 0 top
PC1100  1000P_0402_50V7K  [C_0402]  263.12 47.33 180 top
PC1101  0.1U_0402_25V6  [C_0402]  266.09 40.74 270 top
PC1102  0.01UF_0402_25V7K  [C_0402]  263.11 46.45 270 top
PC1103  1000P_0402_50V7K  [C_0402]  263.31 53.52 90 top
PC1104  2200P_0402_50V7K  [C_0402]  262.22 46.45 270 top
PC1105  1000P_0402_50V7K  [C_0402]  262.41 52.1 270 top
PC1106  470P_0402_50V8J  [C_0402]  259.47 45.42 0 bottom
PC1107  6800P_0402_25V7K  [C_0402]  262.72 50.01 270 top
PC1108  15P_0402_50V8J  [C_0402]  264.52 49.11 180 top
PC1109  1000P_0402_50V7K  [C_0402]  259.22 52.22 0 bottom
PC1110  2200P_0402_50V7K  [C_0402]  259.22 53.17 0 bottom
PC1111  1000P_0402_50V7K  [C_0402]  260.71 37.61 180 top
PC1112  2200P_0402_50V7K  [C_0402]  259.8 39.4 270 top
PC1113  15P_0402_50V8J  [C_0402]  258.85 50.36 90 top
PC1114  470P_0402_50V8J  [C_0402]  260.63 52.17 270 top
PC1115  2200P_0402_50V7K  [C_0402]  257.95 52.15 0 top
PC1116  470P_0402_50V8J  [C_0402]  258.93 36.72 180 top
PC1117  15P_0402_50V8J  [C_0402]  258.04 38.5 180 top
PC1118  470P_0402_50V8J  [C_0402]  257.96 48.01 90 bottom
PC1119  2200P_0402_50V7K  [C_0402]  257.14 36.71 90 top
PC1120  470P_0402_50V8J  [C_0402]  257.84 41.47 90 bottom
PC1121  100P_0402_50V8J  [C_0402]  256.2 51.26 180 top
PC1122  1000P_0402_50V7K  [C_0402]  255.28 50.38 0 top
PC1123  0.1U_0402_25V7K  [C_0402]  256.18 48.01 90 bottom
PC1124  100P_0402_50V8J  [C_0402]  254.48 37.61 180 top
PC1125  1000P_0402_50V7K  [C_0402]  254.48 36.72 180 top
PC1126  0.1U_0402_25V7K  [C_0402]  256.95 41.47 90 bottom
PC1127  0.1U_0402_25V6  [C_0402]  251.37 48.15 180 bottom
PC1128  0.01U_0402_50V7K  [C_0402]  250.46 47.26 0 bottom
PC1129  0.1U_0402_25V6  [C_0402]  256.06 41.47 90 bottom
PC1130  1U_0603_10V6K  [C_0603]  251.29 46.18 180 bottom
PC1131  0.1U_0402_25V6  [C_0402]  254.15 51.28 270 top
PC1132  0.1U_0402_25V6  [C_0402]  251.22 39.52 0 top
PC1133  0.1U_0402_25V6  [C_0402]  253.26 51.28 270 top
PC1134  0.1U_0402_25V6  [C_0402]  251.22 40.53 0 top
PC1135  0.1U_0402_25V6  [C_0402]  252.37 51.28 270 top
PC1136  0.1U_0402_25V6  [C_0402]  251.22 41.55 0 top
PC1140  1000P_0402_50V7K  [C_0402]  265.07 52.1 270 top
PC1141  100U_25V_M  [C_EEEFK1E101YP]  240.73 34.18 0 top
PC1142  100U_25V_M  [C_EEEFK1E101YP]  240.22 19.51 0 top
PC1200  10U_0805_25V6K  [C_0805]  247.08 54 0 bottom
PC1201  10U_0805_25V6K  [C_0805]  247.08 55.71 0 bottom
PC1202  10U_0805_25V6K  [C_0805]  247.08 55.71 0 top
PC1203  10U_0805_25V6K  [C_0805]  247.08 54 0 top
PC1204  10U_0805_25V6K  [C_0805]  242.93 53.04 180 top
PC1205  10U_0805_25V6K  [C_0805]  242.94 58.31 180 top
PC1206  10U_0805_25V6K  [C_0805]  242.94 56.6 180 top
PC1207  10U_0805_25V6K  [C_0805]  242.94 54.88 180 top
PC1208  0.22U_0603_25V7-K  [C_0603]  242.86 51.07 0 bottom
PC1209  1U_0603_10V6K  [C_0603]  233.58 58.38 180 bottom
PC1210  0.22U_0603_25V7-K  [C_0603]  242.99 61.23 0 bottom
PC1211  1U_0603_10V6K  [C_0603]  233.63 48.22 180 bottom
PC1212  1U_0603_10V6K  [C_0603]  235.93 59.61 180 bottom
PC1213  1U_0603_10V6K  [C_0603]  235.98 49.45 180 bottom
PC1214  2200P_0603_50V7K  [C_0603]  235.29 66 90 bottom
PC1215  2200P_0603_50V7K  [C_0603]  235.29 55.84 90 bottom
PC1216  10U_0805_25V6K  [C_0805]  245.91 49.87 0 top
PC1217  10U_0805_25V6K  [C_0805]  242.94 48.15 180 top
PC1218  10U_0805_25V6K  [C_0805]  242.94 46.44 180 top
PC1219  10U_0805_25V6K  [C_0805]  242.94 44.72 180 top
PC1220  22U_0603_6.3V6M  [C_0603]  214.53 46.12 270 top
PC1221  22U_0603_6.3V6M  [C_0603]  214.53 48.72 270 bottom
PC1222  22U_0603_6.3V6M  [C_0603]  214.53 51.33 270 top
PC1223  22U_0603_6.3V6M  [C_0603]  213.26 46.12 270 top
PC1224  22U_0603_6.3V6M  [C_0603]  214.53 51.33 270 bottom
PC1225  22U_0603_6.3V6M  [C_0603]  214.53 46.12 270 bottom
PC1226  22U_0603_6.3V6M  [C_0603]  213.26 48.72 270 bottom
PC1227  22U_0603_6.3V6M  [C_0603]  213.26 46.12 270 bottom
PC1228  22U_0603_6.3V6M  [C_0603]  213.26 51.33 270 bottom
PC1229  22U_0603_6.3V6M  [C_0603]  213.26 51.33 270 top
PC1230  22U_0603_6.3V6M  [C_0603]  215.24 53.93 270 top
PC1231  22U_0603_6.3V6M  [C_0603]  213.51 53.93 270 bottom
PC1232  22U_0603_6.3V6M  [C_0603]  214.53 48.72 270 top
PC1233  22U_0603_6.3V6M  [C_0603]  212.24 53.93 270 bottom
PC1234  22U_0603_6.3V6M  [C_0603]  213.26 53.93 270 top
PC1235  22U_0603_6.3V6M  [C_0603]  213.26 48.72 270 top
PC1236  330U_D2_2.5V_R6M  [C_D2]  216.75 61.2 270 bottom
PC1237  330U_D2_2.5V_R6M  [C_D2]  221.72 61.13 270 bottom
PC1238  10U_0402_6.3V6M  [C_0402]  192.86 53.51 180 bottom
PC1239  10U_0402_6.3V6M  [C_0402]  189.3 48.94 180 bottom
PC1240  10U_0402_6.3V6M  [C_0402]  189.32 50.39 180 bottom
PC1241  10U_0402_6.3V6M  [C_0402]  179.72 49 0 bottom
PC1242  10U_0402_6.3V6M  [C_0402]  181.37 49.89 0 bottom
PC1243  10U_0402_6.3V6M  [C_0402]  187.46 52.68 180 bottom
PC1244  10U_0402_6.3V6M  [C_0402]  191.08 51.16 180 bottom
PC1245  10U_0402_6.3V6M  [C_0402]  179.81 47.72 270 bottom
PC1246  10U_0402_6.3V6M  [C_0402]  191.08 54.21 180 bottom
PC1247  10U_0402_6.3V6M  [C_0402]  179.57 50.91 0 bottom
PC1248  10U_0402_6.3V6M  [C_0402]  191.1 52.69 180 bottom
PC1249  1U_0603_10V6K  [C_0603]  237.01 36.91 0 bottom
PC1250  0.22U_0603_25V7-K  [C_0603]  242.91 40.63 0 bottom
PC1251  10U_0402_6.3V6M  [C_0402]  192.83 47.6 180 bottom
PC1252  10U_0402_6.3V6M  [C_0402]  189.29 51.93 180 bottom
PC1253  10U_0402_6.3V6M  [C_0402]  189.31 53.38 180 bottom
PC1254  10U_0402_6.3V6M  [C_0402]  181.36 51.55 0 bottom
PC1255  10U_0402_6.3V6M  [C_0402]  192.87 50.44 180 bottom
PC1256  10U_0402_6.3V6M  [C_0402]  187.53 49.6 180 bottom
PC1257  10U_0402_6.3V6M  [C_0402]  187.53 51.11 180 bottom
PC1258  1U_0603_10V6K  [C_0603]  235.98 39.26 180 bottom
PC1259  10U_0402_6.3V6M  [C_0402]  192.86 51.92 180 bottom
PC1260  10U_0402_6.3V6M  [C_0402]  181.37 48.11 0 bottom
PC1261  10U_0402_6.3V6M  [C_0402]  189.3 47.48 180 bottom
PC1262  10U_0402_6.3V6M  [C_0402]  191.08 48.24 180 bottom
PC1263  10U_0402_6.3V6M  [C_0402]  181.3 53.26 0 bottom
PC1264  10U_0402_6.3V6M  [C_0402]  179.65 54.15 0 bottom
PC1265  10U_0402_6.3V6M  [C_0402]  191.09 49.64 180 bottom
PC1266  10U_0402_6.3V6M  [C_0402]  192.84 48.99 180 bottom
PC1267  10U_0402_6.3V6M  [C_0402]  187.5 48.18 180 bottom
PC1268  10U_0402_6.3V6M  [C_0402]  187.48 54.14 180 bottom
PC1269  2200P_0603_50V7K  [C_0603]  235.29 45.68 90 bottom
PC1270  1U_0201_4V6M  [C_0201]  208.96 51.74 180 top
PC1271  1U_0201_4V6M  [C_0201]  208.96 57.14 180 top
PC1272  1U_0201_4V6M  [C_0201]  216.78 51.17 180 bottom
PC1273  1U_0201_4V6M  [C_0201]  208.96 54.98 180 top
PC1274  1U_0201_4V6M  [C_0201]  183.54 50.23 270 bottom
PC1275  1U_0201_4V6M  [C_0201]  184.63 48.58 270 bottom
PC1276  1U_0201_4V6M  [C_0201]  183.52 52.01 270 bottom
PC1277  1U_0201_4V6M  [C_0201]  184.03 48.58 270 bottom
PC1278  1U_0201_4V6M  [C_0201]  183.43 48.58 270 bottom
PC1279  1U_0201_4V6M  [C_0201]  185.31 52.01 270 bottom
PC1280  1U_0201_4V6M  [C_0201]  184.71 52.01 270 bottom
PC1281  1U_0201_4V6M  [C_0201]  184.76 54.02 270 bottom
PC1282  1U_0201_4V6M  [C_0201]  208.96 47.04 180 top
PC1283  1U_0201_4V6M  [C_0201]  210.3 45.83 180 top
PC1284  1U_0201_4V6M  [C_0201]  207.76 50.98 180 top
PC1285  1U_0201_4V6M  [C_0201]  207.69 45.83 180 top
PC1286  1U_0201_4V6M  [C_0201]  209.03 44.56 180 top
PC1287  1U_0201_4V6M  [C_0201]  208.96 49.64 180 top
PC1288  1U_0201_4V6M  [C_0201]  219.25 49.71 180 bottom
PC1289  1U_0201_4V6M  [C_0201]  210.17 50.4 180 top
PC1290  1U_0201_4V6M  [C_0201]  219.38 48.37 180 bottom
PC1291  1U_0201_4V6M  [C_0201]  210.26 48.31 180 top
PC1292  1U_0201_4V6M  [C_0201]  184.74 50.23 270 bottom
PC1293  1U_0201_4V6M  [C_0201]  216.97 47.1 180 bottom
PC1294  1U_0201_4V6M  [C_0201]  216.9 48.37 180 bottom
PC1295  1U_0201_4V6M  [C_0201]  216.9 49.71 180 bottom
PC1296  1U_0201_4V6M  [C_0201]  218.17 46.4 180 bottom
PC1297  1U_0201_4V6M  [C_0201]  210.26 47.74 180 top
PC1298  1U_0201_4V6M  [C_0201]  207.69 45.26 180 top
PC1299  1U_0201_4V6M  [C_0201]  207.72 48.3 180 top
PC1300  1U_0201_4V6M  [C_0201]  218.05 50.47 180 bottom
PC1301  1U_0201_4V6M  [C_0201]  210.17 59.17 180 top
PC1302  1U_0201_4V6M  [C_0201]  210.11 53.07 180 top
PC1303  1U_0201_4V6M  [C_0201]  208.96 57.71 180 top
PC1304  1U_0201_4V6M  [C_0201]  207.76 55.74 180 top
PC1305  1U_0201_4V6M  [C_0201]  185.33 50.23 270 bottom
PC1306  1U_0201_4V6M  [C_0201]  184.17 54.02 270 bottom
PC1307  1U_0201_4V6M  [C_0201]  219.51 45.71 180 bottom
PC1308  1U_0201_4V6M  [C_0201]  184.14 50.23 270 bottom
PC1309  1U_0201_4V6M  [C_0201]  185.22 48.58 270 bottom
PC1310  1U_0201_4V6M  [C_0201]  184.12 52.01 270 bottom
PC1311  1U_0201_4V6M  [C_0201]  210.3 45.26 180 top
PC1312  1U_0201_4V6M  [C_0201]  207.76 53.07 180 top
PC1313  1U_0201_4V6M  [C_0201]  207.76 53.64 180 top
PC1314  1U_0201_4V6M  [C_0201]  210.17 55.74 180 top
PC1315  1U_0201_4V6M  [C_0201]  185.36 54.02 270 bottom
PC1316  1U_0201_4V6M  [C_0201]  210.17 56.31 180 top
PC1317  1U_0201_4V6M  [C_0201]  207.76 56.31 180 top
PC1318  1U_0201_4V6M  [C_0201]  207.76 50.4 180 top
PC1319  1U_0201_4V6M  [C_0201]  208.96 49.07 180 top
PC1320  1U_0201_4V6M  [C_0201]  209.03 43.99 180 top
PC1321  1U_0201_4V6M  [C_0201]  207.72 47.73 180 top
PC1322  1U_0201_4V6M  [C_0201]  219.38 47.1 180 bottom
PC1323  1U_0201_4V6M  [C_0201]  210.11 53.64 180 top
PC1324  1U_0201_4V6M  [C_0201]  208.96 54.41 180 top
PC1325  1U_0201_4V6M  [C_0201]  210.17 50.98 180 top
PC1326  1U_0201_4V6M  [C_0201]  208.96 46.47 180 top
PC1327  1U_0201_4V6M  [C_0201]  183.57 54.02 270 bottom
PC1328  1U_0201_4V6M  [C_0201]  219.25 51.17 180 bottom
PC1329  1U_0201_4V6M  [C_0201]  210.17 58.6 180 top
PC1330  1U_0201_4V6M  [C_0201]  218.17 47.74 180 bottom
PC1331  1U_0201_4V6M  [C_0201]  208.96 52.31 180 top
PC1332  1U_0201_4V6M  [C_0201]  218.11 49.01 180 bottom
PC1333  0.1U_0402_25V6  [C_0402]  242.03 61.45 180 top
PC1334  2200P_0402_50V7K  [C_0402]  242.04 60.47 180 top
PC1335  0.1U_0402_25V6  [C_0402]  242.5 57.54 180 bottom
PC1336  2200P_0402_50V7K  [C_0402]  242.5 56.59 180 bottom
PC1337  0.1U_0402_25V6  [C_0402]  241.98 47.14 180 bottom
PC1338  2200P_0402_50V7K  [C_0402]  241.98 46.18 180 bottom
PC1400  10U_0805_25V6K  [C_0805]  242.76 13.23 0 top
PC1401  10U_0805_25V6K  [C_0805]  242.76 11.45 0 top
PC1402  10U_0805_25V6K  [C_0805]  241.72 24.78 0 top
PC1403  10U_0805_25V6K  [C_0805]  242.76 14.94 0 top
PC1404  10U_0805_25V6K  [C_0805]  241.72 26.56 0 top
PC1405  10U_0805_25V6K  [C_0805]  245.94 48.09 0 bottom
PC1406  10U_0805_25V6K  [C_0805]  245.94 46.38 0 bottom
PC1407  10U_0805_25V6K  [C_0805]  245.94 48.09 0 top
PC1408  0.22U_0603_25V7-K  [C_0603]  237.02 14.63 0 top
PC1409  1U_0603_10V6K  [C_0603]  227.61 27.64 180 top
PC1410  0.22U_0603_25V7-K  [C_0603]  236.99 25.04 0 top
PC1411  1U_0603_10V6K  [C_0603]  227.61 17.43 180 top
PC1412  1U_0603_10V6K  [C_0603]  229.96 16.23 180 top
PC1413  1U_0603_10V6K  [C_0603]  229.96 26.44 180 top
PC1414  2200P_0603_50V7K  [C_0603]  229.32 9.86 270 top
PC1415  2200P_0603_50V7K  [C_0603]  229.32 20.02 270 top
PC1416  22U_0603_6.3V6M  [C_0603]  213.12 29.2 90 top
PC1417  22U_0603_6.3V6M  [C_0603]  214.39 29.2 90 top
PC1418  22U_0603_6.3V6M  [C_0603]  214.37 35.01 90 top
PC1419  22U_0603_6.3V6M  [C_0603]  213.18 35.01 90 top
PC1420  22U_0603_6.3V6M  [C_0603]  214.4 38.05 90 bottom
PC1421  22U_0603_6.3V6M  [C_0603]  213.14 38.05 90 bottom
PC1422  22U_0603_6.3V6M  [C_0603]  213.15 32.15 90 bottom
PC1423  22U_0603_6.3V6M  [C_0603]  214.41 35.01 90 bottom
PC1424  22U_0603_6.3V6M  [C_0603]  213.19 41.04 90 bottom
PC1425  22U_0603_6.3V6M  [C_0603]  214.38 41.04 90 bottom
PC1426  22U_0603_6.3V6M  [C_0603]  214.34 41.04 90 top
PC1427  22U_0603_6.3V6M  [C_0603]  213.09 41.04 90 top
PC1428  22U_0603_6.3V6M  [C_0603]  214.34 32.15 90 bottom
PC1429  22U_0603_6.3V6M  [C_0603]  213.12 35.01 90 bottom
PC1430  22U_0603_6.3V6M  [C_0603]  214.4 38.05 90 top
PC1431  22U_0603_6.3V6M  [C_0603]  213.14 38.05 90 top
PC1432  330U 2.5V M D2 LESR6M  [C_D2]  220.7 6.24 0 top
PC1433  10U_0805_25V6K  [C_0805]  241.72 28.34 0 top
PC1434  10U_0805_25V6K  [C_0805]  245.94 44.66 0 top
PC1435  330U 2.5V M D2 LESR6M  [C_D2]  216.64 6.24 180 top
PC1436  10U_0805_25V6K  [C_0805]  245.94 46.38 0 top
PC1437  10U_0805_25V6K  [C_0805]  245.94 44.66 0 bottom
PC1438  0.22U_0603_25V7-K  [C_0603]  236.97 34.95 0 top
PC1439  22U_0603_6.3V6M  [C_0603]  214.37 32.15 90 top
PC1440  22U_0603_6.3V6M  [C_0603]  213.12 29.2 90 bottom
PC1441  22U_0603_6.3V6M  [C_0603]  214.39 29.2 90 bottom
PC1442  22U_0603_6.3V6M  [C_0603]  213.14 32.15 90 top
PC1443  10U_0402_6.3V6M  [C_0402]  188.99 40.05 180 bottom
PC1444  10U_0402_6.3V6M  [C_0402]  188.99 41.5 180 bottom
PC1445  10U_0402_6.3V6M  [C_0402]  192.61 34.5 180 bottom
PC1446  10U_0402_6.3V6M  [C_0402]  192.61 37.28 180 bottom
PC1447  10U_0402_6.3V6M  [C_0402]  187.22 35.11 180 bottom
PC1448  10U_0402_6.3V6M  [C_0402]  187.22 36.56 180 bottom
PC1449  10U_0402_6.3V6M  [C_0402]  187.22 37.94 180 bottom
PC1450  10U_0402_6.3V6M  [C_0402]  192.61 38.69 180 bottom
PC1451  10U_0402_6.3V6M  [C_0402]  190.77 35.13 180 bottom
PC1452  10U_0402_6.3V6M  [C_0402]  192.61 42.92 180 bottom
PC1453  10U_0402_6.3V6M  [C_0402]  192.61 41.51 180 bottom
PC1454  10U_0402_6.3V6M  [C_0402]  192.61 40.1 180 bottom
PC1455  10U_0402_6.3V6M  [C_0402]  192.61 35.9 180 bottom
PC1456  10U_0402_6.3V6M  [C_0402]  187.22 40.78 180 bottom
PC1457  1U_0603_10V6K  [C_0603]  227.63 37.8 180 top
PC1458  1U_0603_10V6K  [C_0603]  229.98 36.6 180 top
PC1459  10U_0402_6.3V6M  [C_0402]  187.22 39.37 180 bottom
PC1460  10U_0402_6.3V6M  [C_0402]  187.15 42.15 180 bottom
PC1461  10U_0402_6.3V6M  [C_0402]  180.53 42.65 0 bottom
PC1462  10U_0402_6.3V6M  [C_0402]  190.83 43.39 180 bottom
PC1463  10U_0402_6.3V6M  [C_0402]  187.22 43.44 180 bottom
PC1464  10U_0402_6.3V6M  [C_0402]  188.99 38.67 180 bottom
PC1465  10U_0402_6.3V6M  [C_0402]  180.54 41.69 0 bottom
PC1466  10U_0402_6.3V6M  [C_0402]  180.54 40.25 0 bottom
PC1467  10U_0402_6.3V6M  [C_0402]  180.6 38.92 0 bottom
PC1468  10U_0402_6.3V6M  [C_0402]  188.99 35.82 180 bottom
PC1469  10U_0402_6.3V6M  [C_0402]  188.99 37.27 180 bottom
PC1470  10U_0402_6.3V6M  [C_0402]  188.99 34.53 180 bottom
PC1471  10U_0402_6.3V6M  [C_0402]  190.77 42.14 180 bottom
PC1472  10U_0402_6.3V6M  [C_0402]  190.77 40.79 180 bottom
PC1473  10U_0402_6.3V6M  [C_0402]  190.77 39.38 180 bottom
PC1474  10U_0402_6.3V6M  [C_0402]  179.16 40.03 270 bottom
PC1475  10U_0402_6.3V6M  [C_0402]  179.16 42.32 270 bottom
PC1476  10U_0402_6.3V6M  [C_0402]  180.66 34.59 0 bottom
PC1477  2200P_0603_50V7K  [C_0603]  229.32 30.18 270 top
PC1478  10U_0402_6.3V6M  [C_0402]  190.77 38 180 bottom
PC1479  10U_0402_6.3V6M  [C_0402]  190.77 36.59 180 bottom
PC1480  10U_0402_6.3V6M  [C_0402]  188.99 42.86 180 bottom
PC1481  1U_0201_4V6M  [C_0201]  210.3 34.97 180 top
PC1482  1U_0201_4V6M  [C_0201]  208.9 42.53 180 top
PC1483  1U_0201_4V6M  [C_0201]  183.4 40.68 90 bottom
PC1484  1U_0201_4V6M  [C_0201]  185.12 43.11 270 bottom
PC1485  1U_0201_4V6M  [C_0201]  209.09 26.21 180 top
PC1486  1U_0201_4V6M  [C_0201]  207.63 40.5 180 top
PC1487  1U_0201_4V6M  [C_0201]  207.76 35.48 180 top
PC1488  1U_0201_4V6M  [C_0201]  185.23 36.18 270 bottom
PC1489  1U_0201_4V6M  [C_0201]  184.63 36.18 270 bottom
PC1490  1U_0201_4V6M  [C_0201]  184.04 36.18 270 bottom
PC1491  1U_0201_4V6M  [C_0201]  183.44 36.18 270 bottom
PC1492  1U_0201_4V6M  [C_0201]  184 40.68 90 bottom
PC1493  1U_0201_4V6M  [C_0201]  184.6 40.68 90 bottom
PC1494  1U_0201_4V6M  [C_0201]  207.69 37.7 180 top
PC1495  1U_0201_4V6M  [C_0201]  210.3 32.18 180 top
PC1496  1U_0201_4V6M  [C_0201]  182.84 36.18 270 bottom
PC1497  1U_0201_4V6M  [C_0201]  209.03 34.15 180 top
PC1498  1U_0201_4V6M  [C_0201]  209.09 28.81 180 top
PC1499  1U_0201_4V6M  [C_0201]  209.09 25.64 180 top
PC1500  1U_0201_4V6M  [C_0201]  210.36 29.51 180 top
PC1501  1U_0201_4V6M  [C_0201]  182.21 36.18 270 bottom
PC1502  1U_0201_4V6M  [C_0201]  185.19 40.68 90 bottom
PC1503  1U_0201_4V6M  [C_0201]  210.3 32.75 180 top
PC1504  1U_0201_4V6M  [C_0201]  182.33 39.61 270 bottom
PC1505  1U_0201_4V6M  [C_0201]  207.63 41.07 180 top
PC1506  1U_0201_4V6M  [C_0201]  185.31 39.61 270 bottom
PC1507  1U_0201_4V6M  [C_0201]  184.71 39.61 270 bottom
PC1508  1U_0201_4V6M  [C_0201]  184.12 39.61 270 bottom
PC1509  1U_0201_4V6M  [C_0201]  183.52 39.61 270 bottom
PC1510  1U_0201_4V6M  [C_0201]  182.92 39.61 270 bottom
PC1511  1U_0201_4V6M  [C_0201]  207.82 32.75 180 top
PC1512  1U_0201_4V6M  [C_0201]  207.76 27.54 180 top
PC1513  1U_0201_4V6M  [C_0201]  209.09 28.24 180 top
PC1514  1U_0201_4V6M  [C_0201]  207.82 29.51 180 top
PC1515  1U_0201_4V6M  [C_0201]  208.96 39.1 180 top
PC1516  1U_0201_4V6M  [C_0201]  210.3 35.55 180 top
PC1517  1U_0201_4V6M  [C_0201]  210.23 41.07 180 top
PC1518  1U_0201_4V6M  [C_0201]  182.81 40.68 90 bottom
PC1519  1U_0201_4V6M  [C_0201]  208.96 39.67 180 top
PC1520  1U_0201_4V6M  [C_0201]  207.76 34.91 180 top
PC1521  1U_0201_4V6M  [C_0201]  209.09 31.42 180 top
PC1522  1U_0201_4V6M  [C_0201]  208.9 41.96 180 top
PC1523  1U_0201_4V6M  [C_0201]  210.36 30.08 180 top
PC1524  1U_0201_4V6M  [C_0201]  182.21 40.68 90 bottom
PC1525  1U_0201_4V6M  [C_0201]  185.19 37.3 90 bottom
PC1526  1U_0201_4V6M  [C_0201]  182.8 37.3 90 bottom
PC1527  1U_0201_4V6M  [C_0201]  183.4 37.3 90 bottom
PC1528  1U_0201_4V6M  [C_0201]  209.03 36.31 180 top
PC1529  1U_0201_4V6M  [C_0201]  184.59 37.3 90 bottom
PC1530  1U_0201_4V6M  [C_0201]  210.23 37.7 180 top
PC1531  1U_0201_4V6M  [C_0201]  209.09 30.85 180 top
PC1532  1U_0201_4V6M  [C_0201]  207.82 30.08 180 top
PC1533  1U_0201_4V6M  [C_0201]  184.52 43.11 270 bottom
PC1534  1U_0201_4V6M  [C_0201]  183.92 43.11 270 bottom
PC1535  1U_0201_4V6M  [C_0201]  183.33 43.11 270 bottom
PC1536  1U_0201_4V6M  [C_0201]  182.73 43.11 270 bottom
PC1537  1U_0201_4V6M  [C_0201]  209.03 33.58 180 top
PC1538  1U_0201_4V6M  [C_0201]  207.76 26.97 180 top
PC1539  1U_0201_4V6M  [C_0201]  207.82 32.18 180 top
PC1540  1U_0201_4V6M  [C_0201]  210.23 38.28 180 top
PC1541  1U_0201_4V6M  [C_0201]  207.69 38.28 180 top
PC1542  1U_0201_4V6M  [C_0201]  209.03 36.88 180 top
PC1543  1U_0201_4V6M  [C_0201]  182.21 37.25 90 bottom
PC1544  1U_0201_4V6M  [C_0201]  210.36 27.54 180 top
PC1545  1U_0201_4V6M  [C_0201]  210.36 26.97 180 top
PC1546  1U_0201_4V6M  [C_0201]  179.07 34.69 90 bottom
PC1547  1U_0201_4V6M  [C_0201]  183.99 37.3 90 bottom
PC1548  1U_0201_4V6M  [C_0201]  210.23 40.5 180 top
PC1549  330U 2.5V M D2 LESR6M  [C_D2]  218.47 36.74 270 bottom
PC1550  0.1U_0402_25V6  [C_0402]  235.84 9.06 180 top
PC1551  2200P_0402_50V7K  [C_0402]  235.87 8.17 180 top
PC1552  0.1U_0402_25V6  [C_0402]  235.7 19.59 180 top
PC1553  2200P_0402_50V7K  [C_0402]  235.7 18.7 180 top
PC1554  0.1U_0402_25V6  [C_0402]  235.98 29.7 180 top
PC1555  2200P_0402_50V7K  [C_0402]  235.99 28.75 180 top
PC1600  470P_0402_50V8J  [C_0402]  261.8 31.09 180 top
PC1601  10U_0805_25V6K  [C_0805]  252.69 28.81 270 top
PC1602  10U_0805_25V6K  [C_0805]  250.98 28.81 270 top
PC1603  0.01UF_0402_25V7K  [C_0402]  263.17 28.29 90 top
PC1604  10U_0805_25V6K  [C_0805]  252.69 31.05 90 top
PC1605  10U_0805_25V6K  [C_0805]  250.98 31.05 90 top
PC1606  1U_0603_10V6K  [C_0603]  260.66 33.56 270 top
PC1607  1000P_0402_50V7K  [C_0402]  264.98 26.83 0 top
PC1608  0.015U_0402_16V7K  [C_0402]  263.52 25.94 270 top
PC1609  15P_0402_50V8J  [C_0402]  264.39 25.94 0 top
PC1610  2200P_0603_50V7K  [C_0603]  252.18 23.9 270 top
PC1611  4.7U_0402_6.3V6M  [C_0402]  259.14 22.93 270 top
PC1612  470P_0402_50V8J  [C_0402]  262.09 25.22 180 top
PC1613  0.22U_0603_25V7-K  [C_0603]  254.44 32.04 90 top
PC1614  1000P_0402_50V7K  [C_0402]  263.84 22.64 180 top
PC1615  10U_0402_6.3V6M  [C_0402]  192.61 46.3 180 bottom
PC1616  10U_0402_6.3V6M  [C_0402]  189.87 46.06 0 bottom
PC1617  10U_0402_6.3V6M  [C_0402]  189.93 44.42 0 bottom
PC1618  10U_0402_6.3V6M  [C_0402]  192.61 44.93 180 bottom
PC1619  22U_0603_6.3V6M  [C_0603]  200.3 14.16 180 top
PC1620  22U_0603_6.3V6M  [C_0603]  195.93 13.59 180 bottom
PC1621  22U_0603_6.3V6M  [C_0603]  195.93 14.84 180 bottom
PC1622  22U_0603_6.3V6M  [C_0603]  195.93 16.04 180 bottom
PC1623  22U_0603_6.3V6M  [C_0603]  194.92 17.29 180 bottom
PC1624  22U_0603_6.3V6M  [C_0603]  200.3 10.54 180 top
PC1625  22U_0603_6.3V6M  [C_0603]  200.3 11.74 180 top
PC1626  22U_0603_6.3V6M  [C_0603]  200.3 12.95 180 top
PC1627  1000P_0402_50V7K  [C_0402]  264.73 22.7 270 top
PC1628  1U_0201_4V6M  [C_0201]  188.94 44.44 180 bottom
PC1629  1U_0201_4V6M  [C_0201]  188.94 45.54 180 bottom
PC1630  1U_0201_4V6M  [C_0201]  183.86 46.58 180 bottom
PC1631  1U_0201_4V6M  [C_0201]  185.06 45.97 180 bottom
PC1632  1U_0201_4V6M  [C_0201]  183.86 45.43 180 bottom
PC1633  1U_0201_4V6M  [C_0201]  185.06 44.88 180 bottom
PC1634  1U_0201_4V6M  [C_0201]  186.33 44.34 180 bottom
PC1635  1U_0201_4V6M  [C_0201]  186.33 46.58 180 bottom
PC1636  1U_0201_4V6M  [C_0201]  187.6 44.96 180 bottom
PC1637  1U_0201_4V6M  [C_0201]  187.6 46.06 180 bottom
PC1638  1U_0201_4V6M  [C_0201]  186.32 45.51 180 bottom
PC1639  1U_0201_4V6M  [C_0201]  188.94 46.59 180 bottom
PC1640  1000P_0402_50V7K  [C_0402]  265.55 20.86 180 top
PC1641  470U_X_2VM_R6M  [C_D2]  200.77 6.24 0 top
PC1642  0.1U_0402_25V7K  [C_0402]  255.82 34.37 180 top
PC1643  0.1U_0402_25V6  [C_0402]  248.62 28.71 270 top
PC1644  2200P_0402_50V7K  [C_0402]  249.57 28.73 270 top
PC1690  4700P_0402_25V7K  [C_0402]  262.29 28.3 90 top
PC1700  10U_0805_25V6K  [C_0805]  237.85 73.9 270 bottom
PC1701  10U_0805_25V6K  [C_0805]  234.95 78.7 180 bottom
PC1702  1U_0603_10V6K  [C_0603]  227.29 68.24 180 bottom
PC1703  0.22U_0603_25V7-K  [C_0603]  236.63 70.95 0 bottom
PC1704  1U_0603_10V6K  [C_0603]  229.64 69.45 180 bottom
PC1705  2200P_0603_50V7K  [C_0603]  230.47 76.66 180 bottom
PC1706  220U_D2_2.5VY_R9M  [C_D2]  217.33 72.23 90 bottom
PC1707  0.1U_0402_25V6  [C_0402]  234.62 76.4 180 bottom
PC1708  2200P_0402_50V7K  [C_0402]  234.6 77.29 180 bottom
PC1800  0.1U_0603_25V7K  [C_0603]  58.08 13.16 270 top
PC1801  680P_0402_50V7K  [C_0402]  61.42 13.6 0 top
PC1802  22U_0603_6.3V6M  [C_0603]  63.89 10.83 90 top
PC1803  22U_0603_6.3V6M  [C_0603]  61.35 10.83 90 top
PC1804  22U_0603_6.3V6M  [C_0603]  62.59 10.83 90 top
PC1805  10U_0603_25V6M  [C_0603]  51.79 9.8 270 top
PC1806  0.1U_0402_25V6  [C_0402]  58.34 5.3 270 top
PC1807  1U_0402_6.3V6K  [C_0402]  55.52 12.58 270 top
PC1808  0.1U_0402_25V6  [C_0402]  54.14 8.41 270 top
PC1809  10U_0603_25V6M  [C_0603]  53.06 9.8 270 top
PC1810  10U_0603_25V6M  [C_0603]  50.4 8.59 270 top
PD1  -  [BAS40CW_SOT323-3]  46.8 29.61 270 bottom
PD2  -  [TVNST52302AB0_SOT523-3]  253.85 9.92 180 top
PD3  -  [TVNST52302AB0_SOT523-3]  251.76 9.92 180 top
PD4  -  [PESD5V0U2BT_SOT23-3]  29.35 43.71 270 top
PD5  -  [SDMK0340L-7-F_SOD323-2]  248.49 7.89 180 top
PD6  -  [PESD5V0U2BT_SOT23-3]  10.96 13.33 0 top
PD8  VZ0603M260APT_0603  [D_0603]  48.62 46.22 270 bottom
PD700  ES2AA-13-F  [SBR3A40SA-13_SMA2]  35.61 40.25 90 bottom
PD701  BAT54CW-7-F SOT-323  [BAT54CW_SOT323-3]  283.22 38.56 90 top
PD702  BAT54CW-7-F SOT-323  [BAT54CW_SOT323-3]  284.33 42.41 0 top
PD703  -  [MM3Z22VST1G_SOD323-2]  278.43 31.15 270 top
